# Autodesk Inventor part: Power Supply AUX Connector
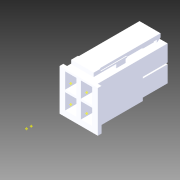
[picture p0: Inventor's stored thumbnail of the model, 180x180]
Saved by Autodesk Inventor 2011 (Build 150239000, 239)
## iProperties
Company: Autodesk Inc.
Created: 2005-12
Part Number: Power Supply AUX Connector
Document SubType Name: Modeling
Designer: Autodesk Inc.
Density: 1 g/cm^3
Categories: <MemberInstance><Categories><Category DisplayName="" Mnemonic="CABLEANDHARNESS" InternalName="e4a7e005-5e42-4d16-b293-125e7f0d0512"><Category DisplayName="" Mne
Mass: 0.775222 g
Surface Area: 23.9211 cm^2
Volume: 0.775222 cm^3
Title: PC Demo
Author: Autodesk Inc.
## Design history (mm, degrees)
sketch "Sketch1"
  geometry: L1 (0, 8.2)-(0, -7.2) reference; L2 (-7.127, 0)-(7.127, 0) reference; L3 (-4.091, 5)-(4.091, 5); L4 (4.091, 5)-(4.091, -5); L5 (4.091, -5)-(-4.091, -5); L6 (-4.091, -5)-(-4.091, 5)
  constraints: 8 end point, 2 parallel, 1 horizontal, 1 perpendicular, 2 other
  dimensions: "d0" = 8.182 distance of L3.start L3.end; "d1" = 10 distance of L5.end L3.start
extrude "Extrusion1" new body sketch "Sketch1" distance "d2" = 10; taper "d3" = 0 deg
workplane "Work Plane1"
sketch "Sketch2"
  geometry: L1 (4.091, 5)-(4.091, -5) reference; L2 (-4.091, 5)-(4.091, 5) reference; L3 (-4.091, -5)-(-4.091, 5) reference; L4 (4.091, -5)-(-4.091, -5) reference
extrude "Extrusion2" join sketch "Sketch2" distance "d5" = 13; taper "d6" = 0 deg
sketch "Sketch3"
  geometry: L1 (4.091, -5)-(-4.091, -5) reference; L2 (4.091, 5)-(4.091, -5) reference; L3 (-4.091, 5)-(4.091, 5) reference; L4 (-4.091, -5)-(-4.091, 5) reference; L5 (5.091, 6)-(5.091, -6); L6 (5.091, -6)-(-5.091, -6); L7 (-5.091, -6)-(-5.091, 6); L8 (-5.091, 6)-(5.091, 6)
  constraints: 8 end point, 3 other
  dimensions: "d7" = 1 distance between parallel lines of L8 L3
extrude "Extrusion3" join sketch "Sketch3" distance "d8" = 1; taper "d9" = 0 deg
sketch "Sketch4"
  geometry: L1 (-4.091, 5)-(4.091, 5) reference; L2 (-4.091, -5)-(-4.091, 5) reference; L3 (4.091, -5)-(-4.091, -5) reference; L4 (4.091, 5)-(4.091, -5) reference; L5 (3.591, 4.5)-(0.591, 4.5); L6 (0.591, 4.5)-(0.591, 0.3); L7 (0.591, 0.3)-(3.591, 0.3); L8 (3.591, 0.3)-(3.591, 4.5); L9 (3.591, -0.3)-(0.591, -0.3); L10 (0.591, -0.3)-(0.591, -4.5); L11 (0.591, -4.5)-(3.591, -4.5); L12 (3.591, -4.5)-(3.591, -0.3)
  constraints: 16 end point, 4 parallel, 3 collinear, 2 horizontal, 2 perpendicular
  dimensions: "d10" = 0.5 distance between parallel lines of L1 L5; "d11" = 0.5 distance between parallel lines of L3 L11 (= d10); "d12" = 4.2 distance of L5.end L6.end; "d13" = 0.5 distance between parallel lines of L4 L8; "d14" = 3 distance of L5.start L5.end
extrude "Extrusion4" cut sketch "Sketch4" distance "d15" = 16; taper "d16" = 0 deg
pattern_linear "Rectangular Pattern1" dims "d19" = 4.182
split "Split1"
sketch "Sketch8"
  geometry: L1 (5.091, -6)-(-5.091, -6) reference; L2 (0, 8.4)-(0, -8.4) reference; L3 (-7.5, -6)-(7.5, -6); L4 (7.5, -6)-(7.5, -5); L5 (7.5, -5)-(-7.5, -5); L6 (-7.5, -5)-(-7.5, -6)
  constraints: 8 end point, 2 parallel, 1 horizontal, 1 perpendicular, 1 point on line, 1 other
  dimensions: "d36" = 15 distance of L4.end L5.end; "d37" = 1 distance of L5.end L3.start
extrude "Extrusion8" cut sketch "Sketch8" stored distance "d38" = 6; taper "d39" = 0 deg
sketch "Sketch5"
  geometry: L1 (8.182, 10)-(0, 10) reference; L2 (4.091, 44.364)-(4.091, -7.394) reference; L3 (2.091, 8)-(6.091, 8); L4 (6.091, 8)-(6.091, 5); L5 (6.091, 5)-(2.091, 5); L6 (2.091, 5)-(2.091, 8)
  constraints: 8 end point, 2 parallel, 1 horizontal, 1 perpendicular, 1 other
  dimensions: "d20" = 4 distance of L4.end L5.end; "d21" = 3 distance of L3.end L4.end; "d22" = 2 distance between parallel lines of L1 L3
extrude "Extrusion5" join sketch "Sketch5" distance "d23" = 1; taper "d24" = 0 deg
sketch "Sketch6"
  geometry: L1 (-5, 10)-(-5, 22) reference; L2 (-5, 5)-(-6, 5) reference; L3 (-6, 8)-(-6, 5) reference; L4 (-6, 4)-(-7, 4); L5 (-7, 4)-(-7, 22); L6 (-7, 22)-(-6, 22); L7 (-6, 22)-(-6, 4); L8 (-6, 5)-(-5.3, 5); L9 (-6, 4)-(-5.3, 5); L10 (-5.3, 5)-(-6, 5); L11 (-5.3, 5)-(-6, 5); L12 (-6, 4)-(-6, 5); 1 further point
  constraints: 18 end point, 4 equal length, 2 perpendicular, 1 collinear, 1 horizontal, 1 point on line
  dimensions: "d25" = 1 distance of L4.start L4.end; "d26" = 1 distance between parallel lines of L4 L2; "d27" = 18 distance of L4.end L5.end; "d28" = 35 deg angle of L7 L9
extrude "Extrusion6" join sketch "Sketch6" stored distance "d29" = 6; taper "d30" = 0 deg
sketch "Sketch7"
  geometry: L1 (6, -18)-(6, 0) reference; L2 (0, 0)-(6, 0) reference; L3 (0, 0)-(0, -18) reference; L4 (0, -6)-(1, -6); L5 (1, -6)-(1, -8.5); L6 (1, -8.5)-(0, -8.5); L7 (0, -8.5)-(0, -6); L8 (6, -6)-(5, -6); L9 (5, -6)-(5, -8.5); L10 (5, -8.5)-(6, -8.5); L11 (6, -8.5)-(6, -6)
  constraints: 16 end point, 4 parallel, 3 collinear, 2 horizontal, 2 perpendicular, 2 point on line
  dimensions: "d31" = 6 distance between parallel lines of L4 L2; "d32" = 2.5 distance of L4.end L5.end; "d33" = 1 distance of L5.end L6.end
extrude "Extrusion7" join sketch "Sketch7" stored distance "d34" = 6; taper "d35" = 0 deg
sketch "Sketch9"
  geometry: L1 (-4, -7)-(-22, -7) reference; L2 (-4, -6)-(-4, -7) reference; L3 (-5, -5.3)-(-4, -6) reference; L4 (-5, -6)-(-5, -5.3) reference; L5 (-13.5, -6)-(-5, -6) reference; L6 (-20.169, -7)-(-20.169, -6.371); L7 (-20.169, -6.371)-(-13.107, -6.371); L8 (-13.107, -6)-(-13.107, -6.371)
  constraints: 6 end point, 2 perpendicular, 2 point on line, 1 parallel
extrude "Extrusion9" cut sketch "Sketch9" distance "d40" = 0.2; taper "d41" = 0 deg
mirror "Mirror1"
sketch "Sketch11"
  geometry: L1 (4.091, 5)-(-4.091, 5) reference; L2 (-4.091, 5)-(-4.091, -5) reference; L3 (-4.091, -5)-(4.091, -5) reference; L4 (4.091, -5)-(4.091, 5) reference; L5 (3.591, 0.3)-(3.591, 4.5) reference; L6 (3.591, 4.5)-(0.591, 4.5) reference; L7 (0.591, 4.5)-(0.591, 0.3) reference; L8 (0.591, 0.3)-(3.591, 0.3) reference; L9 (3.591, -4.5)-(3.591, -0.3) reference; L10 (3.591, -0.3)-(0.591, -0.3) reference; L11 (0.591, -0.3)-(0.591, -4.5) reference; L12 (0.591, -4.5)-(3.591, -4.5) reference; L13 (-0.591, 0.3)-(-0.591, 4.5) reference; L14 (-0.591, 4.5)-(-3.591, 4.5) reference; L15 (-3.591, 4.5)-(-3.591, 0.3) reference; L16 (-3.591, 0.3)-(-0.591, 0.3) reference; L17 (-0.591, -4.5)-(-0.591, -0.3) reference; L18 (-0.591, -0.3)-(-3.591, -0.3) reference; L19 (-3.591, -0.3)-(-3.591, -4.5) reference; L20 (-3.591, -4.5)-(-0.591, -4.5) reference; L21 (-5.091, 6)-(-5.091, -5) reference; L22 (5.091, 6)-(-5.091, 6) reference; L23 (5.091, -5)-(5.091, 6) reference; L24 (5.091, -5)-(-5.091, -5) reference
extrude "Extrusion11" cut sketch "Sketch11" distance "d49" = 10; taper "d50" = 0 deg
sketch "Sketch12"
  geometry: L1 (-0.491, -4.6)-(-3.691, -4.6); L2 (-3.691, -4.6)-(-3.691, -0.2); L3 (-3.691, -0.2)-(-0.491, -0.2); L4 (-0.491, -0.2)-(-0.491, -4.6); L5 (-1.091, -4)-(-3.091, -4); L6 (-3.091, -4)-(-3.091, -0.8); L7 (-3.091, -0.8)-(-1.091, -0.8); L8 (-1.091, -0.8)-(-1.091, -4); L9 (-0.591, -4.5)-(-0.591, -0.3) reference; L10 (-3.591, -4.5)-(-0.591, -4.5) reference; 4 further points
  constraints: 16 end point, 4 midpoint, 4 parallel, 2 horizontal, 2 perpendicular, 1 horizontal alignment, 1 vertical alignment
  dimensions: "d69" = 0.6 distance between parallel lines of L1 L5; "d70" = 0.6 distance between parallel lines of L4 L8; "d71" = 0.6 distance between parallel lines of L3 L7; "d72" = 0.6 distance between parallel lines of L2 L6; "d73" = 4.4 distance of L3.end L1.start; "d74" = 3.2 distance of L2.end L3.end
extrude "Extrusion12" join sketch "Sketch12" distance "d59" = 7; taper "d60" = 0 deg
pattern_linear "Rectangular Pattern3" dims "d63" = 4.182, "d66" = 4.8
workplane "Work Plane2"
workplane "Work Plane3"
sketch "Sketch16"
  geometry: L1 (-5.091, -5)-(5.091, -5) reference; L2 (5.091, 6)-(5.091, -5) reference; L3 (-5.091, 6)-(5.091, 6) reference; L4 (-5.091, -5)-(-5.091, 6) reference; L5 (0.591, -4.5)-(0.591, -0.3) reference; L6 (0.591, -0.3)-(3.591, -0.3) reference; L7 (3.591, -0.3)-(3.591, -4.5) reference; L8 (3.591, -4.5)-(0.591, -4.5) reference; L9 (0.591, 0.3)-(0.591, 4.5) reference; L10 (0.591, 4.5)-(3.591, 4.5) reference; L11 (3.591, 4.5)-(3.591, 0.3) reference; L12 (3.591, 0.3)-(0.591, 0.3) reference; L13 (-3.591, -4.5)-(-3.591, -0.3) reference; L14 (-3.591, -0.3)-(-0.591, -0.3) reference; L15 (-0.591, -0.3)-(-0.591, -4.5) reference; L16 (-0.591, -4.5)-(-3.591, -4.5) reference; L17 (-3.591, 0.3)-(-3.591, 4.5) reference; L18 (-3.591, 4.5)-(-0.591, 4.5) reference; L19 (-0.591, 4.5)-(-0.591, 0.3) reference; L20 (-0.591, 0.3)-(-3.591, 0.3) reference; 12 further points
  constraints: 8 midpoint, 4 horizontal alignment, 4 vertical alignment
node "1"
node "2"
node "3"
node "4"
workplane "Work Plane4"
workplane "Work Plane5"
sketch "Sketch17"
  geometry: L1 (-2.091, -2.4)-(2.091, 2.4); 1 further point
  constraints: 2 end point, 1 midpoint
workpoint "Work Point31"
sketch "Sketch18"
  geometry: 1 further point
workpoint "Work Point32"
body "Solid1"
node "Projected Loop2"
other parameters: "d4" = 0, "d51" = 0.1, "d52" = 0.1, "d53" = 0.1, "d54" = 0.1, "d55" = 0.5, "d56" = 0.5, "d57" = 0.5, "d58" = 0.5, "d67" = 19.05, "d68" = 20.32, "d75" = 12.7, "d76" = 13.97
